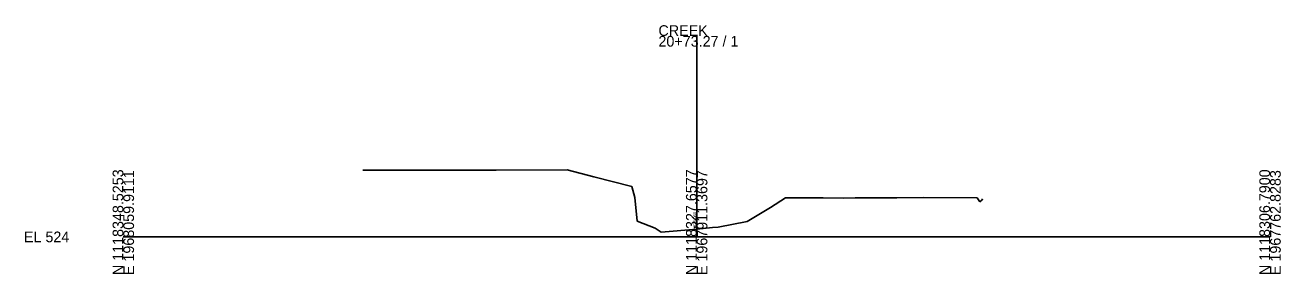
# Model space of a CAD drawing. Extents: x 9974 to 10303, y 9990 to 19550.
# Drawn here: x 9974.3 to 10302.8, y 9990.3 to 10055.5 of the extents above; entities that cross this region are included whole.
import ezdxf

# ---------------------------------------------------------------- set-up
doc = ezdxf.new("R2010")
doc.units = 0
for name, color, linetype in [('Level 10', 7, 'Continuous'), ('Level 60', 7, 'Continuous'), ('Level 63', 7, 'Continuous')]:
    doc.layers.add(name, color=color, linetype=linetype)

msp = doc.modelspace()

# ---------------------------------------------------------------- linework, layer by layer
at = {"layer": 'Level 60'}
for p, q in [((10062.69, 10017.46), (10097.51, 10017.49)), ((10097.51, 10017.49), (10116.08, 10017.55)), ((10116.08, 10017.55), (10123.07, 10015.75)), ((10123.07, 10015.75), (10133.07, 10013.24)), ((10133.07, 10013.24), (10133.82, 10010.29)), ((10133.82, 10010.29), (10134.39, 10004.16)), ((10163.17, 10004.02), (10169.31, 10007.73)), ((10169.31, 10007.73), (10173.27, 10010.19)), ((10173.27, 10010.19), (10183.06, 10010.22)), ((10183.06, 10010.22), (10188.43, 10010.14)), ((10188.43, 10010.14), (10191.5, 10010.27)), ((10191.5, 10010.27), (10202.37, 10010.19)), ((10202.37, 10010.19), (10209.42, 10010.29)), ((10209.42, 10010.29), (10223.39, 10010.26)), ((10223.39, 10010.26), (10224.06, 10009.22)), ((10224.06, 10009.22), (10224.7, 10009.73)), ((10224.7, 10009.73), (10224.75, 10009.97)), ((10134.39, 10004.16), (10139.16, 10002.25)), ((10155.66, 10002.54), (10163.17, 10004.02)), ((10139.16, 10002.25), (10140.68, 10001.25)), ((10140.68, 10001.25), (10150, 10002.06)), ((10150, 10002.06), (10154.15, 10002.42)), ((10154.15, 10002.42), (10155.66, 10002.54))]:
    msp.add_line(p, q, dxfattribs=at)
at = {"layer": 'Level 63'}
for p, q in [((10150, 10000), (10150, 10052.64)), ((10000, 10000), (10150, 10000)), ((10150, 10000), (10300, 10000))]:
    msp.add_line(p, q, dxfattribs=at)

# ---------------------------------------------------------------- texts
at = {"layer": 'Level 10'}
msp.add_text('526.060', height=0.8, rotation=90, dxfattribs=at).set_placement((10149.9, 10002.56))
at = {"layer": 'Level 63'}
for s, p in [('CREEK', (10140, 10052.64)), ('20+73.27 / 1', (10140, 10049.84)), ('EL 524', (9974, 9998.6))]:
    msp.add_text(s, height=2.8, dxfattribs=at).set_placement(p)
for s, p in [('N 1118348.5253', (10000, 9990)), ('E 1968059.9111', (10002.8, 9990)), ('N 1118327.6577', (10150, 9990)), ('E 1967911.3697', (10152.8, 9990)), ('N 1118306.7900', (10300, 9990)), ('E 1967762.8283', (10302.8, 9990))]:
    msp.add_text(s, height=2.8, rotation=90, dxfattribs=at).set_placement(p)

doc.saveas('drawing.dxf')
